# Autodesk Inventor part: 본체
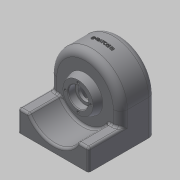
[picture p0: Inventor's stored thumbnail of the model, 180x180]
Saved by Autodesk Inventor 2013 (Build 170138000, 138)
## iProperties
Created: 2015-02
Part Number: 본체
Material: 일반
Document SubType Name: Modeling
Designer: Administrator
Density: 1 g/cm^3
Author: Administrator
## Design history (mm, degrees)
sketch "스케치1"
  geometry: L1 (-50, 0)-(-50, -50); L2 (50, 0)-(50, -50); L3 (50, -50)-(-50, -50); A1 r 50 centre (0, 0) between (50, 0) and (-50, 0); 1 further point
  constraints: 6 end point, 2 point on circle, 2 tangent, 1 centre point, 1 coincident, 1 parallel, 1 perpendicular, 1 vertical
  dimensions: "d0" = 100 diameter of A1; "d1" = 50 distance from line of L3 A1.centre
extrude "돌출1" new body sketch "스케치1" stored distance "d2" = 50; taper "d3" = 0 deg
sketch "스케치3"
  geometry: L1 (50, 50)-(-50, 50); L2 (-50, 50)-(-50, 20); L3 (-50, 20)-(50, 20); L4 (50, 20)-(50, 50)
  constraints: 8 end point, 2 parallel, 1 horizontal, 1 perpendicular
  dimensions: "d4" = 100 distance of L3.end L2.end; "d5" = 30 distance of L2.end L1.end
extrude "돌출2" join sketch "스케치3" distance "d6" = 95; taper "d7" = 0 deg
sketch "스케치5"
  geometry: L1 (-40, 0)-(40, 0); L2 (25, -50)-(-70, -50) reference; L3 (-35, 0)-(-35, 21.36); L4 (-25, 50)-(-25, 0) reference; L5 (-35, 21.36)-(-25, 25); L6 (-25, 25)-(-25, 0); L7 (-35, 0)-(-25, 0); 1 further point
  constraints: 10 end point, 1 collinear, 1 horizontal, 1 midpoint, 1 perpendicular, 1 point on line
  dimensions: "d8" = 50 distance between parallel lines of L1 L2; "d9" = 10 distance between parallel lines of L4 L3; "d10" = 50 diameter of L5.end L1; "d11" = 110 deg angle of L4 L5
sketch "스케치6"
  geometry: L1 (50, -20)-(-50, -20) reference; L2 (-34.641, -20)-(34.641, -20); A1 r 40 centre (0, 0) between (-34.641, -20) and (34.641, -20); 1 further point
  constraints: 2 end point, 2 point on circle, 2 point on line, 1 centre point, 1 coincident, 1 collinear
  dimensions: "d12" = 80 diameter of A1
extrude "돌출3" cut sketch "스케치6" stored distance "d13" = 35; taper "d14" = 0 deg
revolve "회전1" stored, may be unused: angle "d15" = 90 deg
hole "구멍1" diameter "d18" = 20; stored, may be unused: countersink angle "d22" = 90 deg, drill point angle "d24" = 0 deg; dims "d16" = 10, "d17" = 10, "d19" = 6, "d20" = 28, "d21" = 10, "d23" = 4
sketch "스케치7"
  geometry: L1 (25, 0)-(25, 50) reference; L2 (25, -50)-(25, 0) reference; L3 (-29.31, 0)-(29.31, 0); L4 (25, 20)-(34, 20); L5 (34, 20)-(34, 0); L6 (25, 20)-(25, 0); L7 (34, 0)-(25, 0); 2 further points
  constraints: 10 end point, 2 collinear, 2 perpendicular, 1 coincident, 1 midpoint, 1 parallel, 1 point on line
  dimensions: "d27" = 40 diameter of L4 L3; "d29" = 9 distance of L4.start L4.end
revolve "회전2" sketch "스케치7" stored, may be unused: angle "d30" = 90 deg
fillet "모깎기1" dims "d31" = 10
fillet "모깎기2" dims "d32" = 10
fillet "모깎기3" dims "d33" = 3
fillet "모깎기4" dims "d34" = 3
sketch "스케치11"
  geometry: L1 (-50, -20)-(-50, 0) reference; L2 (-50, -50)-(-50, -20) reference; L3 (50, -20)-(50, -50) reference; L4 (50, 0)-(50, -20) reference; L5 (50, 0)-(50, -50) reference; L6 (50, -50)-(-50, -50) reference; L7 (-50, -50)-(-50, 0) reference; L8 (-46, -50)-(-46, -20); L9 (-46, -20)-(-46, 0); L10 (46, 0)-(46, -20); L11 (46, -20)-(46, -50); L12 (-46, -50)-(46, -50); A1 r 50 centre (0, 0) between (50, 0) and (-50, 0) reference; A2 r 50 centre (0, 0) between (50, 0) and (-50, 0) reference; A3 r 46 centre (0, 0) between (46, 0) and (-46, 0); 1 further point
  constraints: 10 end point, 4 parallel, 2 point on circle, 1 centre point, 1 collinear
  dimensions: "d53" = 4 distance between parallel lines of L9 L1; "d54" = 4 radial gap between concentric circles of A3 A1; "d55" = 4 distance between parallel lines of L3 L11
extrude "돌출5" cut sketch "스케치11" stored distance "d56" = 42; taper "d57" = 0 deg
sketch "스케치12" dims "d58" = 36
  geometry: C1 r 14 at (0, 0) reference; C2 r 21.36 at (0, 0) reference; 2 further points
  constraints: 2 vertical alignment, 1 coincident, 2 other
hole "구멍2" sketch "스케치12" at (0, 18) diameter "d59" = 3.459; stored, may be unused: countersink angle "d63" = 90 deg, drill point angle "d65" = 118 deg; dims "d60" = 6, "d61" = 4, "d62" = 2, "d64" = 9
sketch "스케치13"
  geometry: L1 (0, 85)-(0, 0) reference; L2 (100, 0)-(0, 0) reference; 5 further points
  constraints: 2 horizontal alignment, 2 vertical alignment
  dimensions: "d69" = 33 distance of point (8.25, 42) point (8.25, 9); "d71" = 9 distance from line of point (8.25, 9) L2; "d72" = 83.5 distance of point (8.25, 9) point (91.75, 9); "d73" = 8.25 distance from line of L1 point (8.25, 9)
hole "구멍3" sketch "스케치13" at (8.25, 9), (8.25, 42), (91.75, 42), (91.75, 9) diameter "d74" = 5.134; stored, may be unused: countersink angle "d78" = 90 deg, drill point angle "d80" = 118 deg; dims "d75" = 10, "d76" = 4, "d77" = 2, "d79" = 13
node "작업 평면1"
sketch "스케치14"
  geometry: L1 (-40, 25)-(40, 25) reference; 2 further points
  constraints: 1 coincident, 1 other
feature "엠보싱1" sketch "스케치14" dims "d81" = 1, "d82" = 0
hole "구멍4" diameter "d85" = 20; stored, may be unused: countersink angle "d89" = 90 deg, drill point angle "d91" = 0 deg; dims "d83" = 10, "d84" = 10, "d86" = 10, "d87" = 28, "d88" = 8, "d90" = 2
fillet "모깎기5" dims "d92" = 3
fillet "모깎기6" dims "d93" = 3
fillet "모깎기7" dims "d94" = 3
fillet "모깎기8" dims "d95" = 3
fillet "모깎기9" dims "d96" = 3
fillet "모깎기10" dims "d97" = 3
fillet "모깎기11" dims "d98" = 3
fillet "모깎기12" dims "d99" = 6
chamfer "모따기1" distance "d100" = 1; stored, may be unused: second distance "d101" = 2, angle "d102" = 45 deg
fillet "모깎기13" dims "d103" = 0.3
chamfer "모따기2" distance "d104" = 1; stored, may be unused: second distance "d105" = 2, angle "d106" = 45 deg
fillet "모깎기14" dims "d107" = 0.3
fillet "모깎기15" dims "d108" = 3
node "솔리드1"
pattern_circular "원형 패턴1" dims angle "d67" = 360 deg
node "절단 모서리 투영1"
